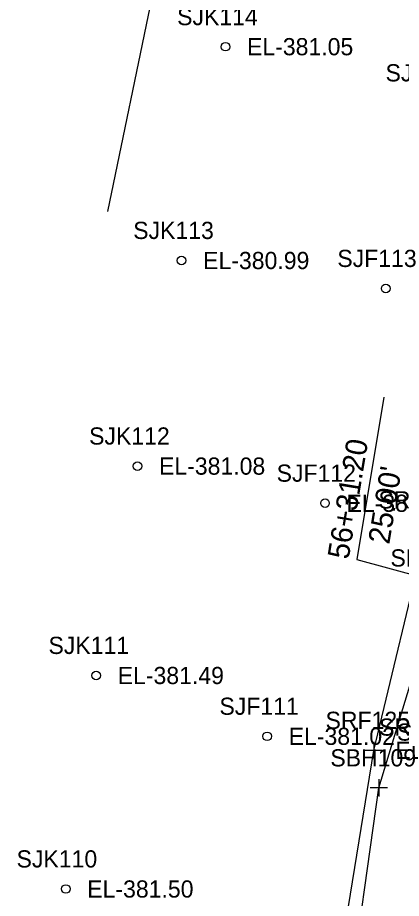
# Model space of a CAD drawing. Extents: x 1189978 to 1314812, y 571533 to 629339.
# Drawn here: x 1217347.2 to 1217436.4, y 621309.2 to 621514.1 of the extents above; entities that cross this region are included whole.
import ezdxf

# ---------------------------------------------------------------- set-up
doc = ezdxf.new("R2010")
doc.units = 0
for name, color, linetype in [('SURVEY - DRAINAGE - Bridge Hydraulic Data with Text', 7, 'Continuous'), ('SURVEY - DTM - Breaklines', 7, 'Continuous'), ('SURVEY - DTM - Breaklines - Points - Elevations', 7, 'Continuous'), ('SURVEY - DTM - Breaklines - Points - Locators', 7, 'Continuous'), ('SURVEY - DTM - Breaklines - Points - Numbers', 7, 'Continuous'), ('SURVEY - DTM - Spot Points - Elevations', 7, 'Continuous'), ('SURVEY - DTM - Spot Points - Locators', 7, 'Continuous'), ('SURVEY - DTM - Spot Points - Point Numbers', 7, 'Continuous'), ('SURVEY - PROPERTY - Station and Offset Flags', 7, 'Continuous'), ('SURVEY - VEGETATION - Features - Points - Locators', 7, 'Continuous'), ('SURVEY - VEGETATION - Features - Points - Numbers', 7, 'Continuous'), ('SURVEY - VEGETATION - Features with Text', 7, 'Continuous')]:
    doc.layers.add(name, color=color, linetype=linetype)

msp = doc.modelspace()

# ---------------------------------------------------------------- linework, layer by layer
at = {"layer": 'SURVEY - DRAINAGE - Bridge Hydraulic Data with Text'}
msp.add_line((1217368.17, 621469.01), (1217394.49, 621596.22), dxfattribs=at)
at = {"layer": 'SURVEY - DTM - Breaklines'}
msp.add_lwpolyline([(1217387.31, 620948.08), (1217393.6, 620996.48), (1217397.69, 621051.02), (1217403.2, 621099.03), (1217410.14, 621143.75), (1217412.38, 621196.49), (1217416.71, 621248.1), (1217421.59, 621292.12), (1217429.99, 621343.65), (1217442.32, 621394.91), (1217455.15, 621442.51), (1217467.64, 621488.57), (1217479.21, 621534.19), (1217491.95, 621583.57), (1217498.28, 621637.4), (1217497.56, 621661.82), (1217450.04, 621674.51)], dxfattribs=at)
at = {"layer": 'SURVEY - DTM - Breaklines - Points - Locators'}
for p, q in [((1217429.99, 621345.65), (1217429.99, 621341.65)), ((1217431.99, 621343.65), (1217427.99, 621343.65))]:
    msp.add_line(p, q, dxfattribs=at)
at = {"layer": 'SURVEY - DTM - Spot Points - Locators'}
for centre in [(1217395.51, 621507.3), (1217385.31, 621457.58), (1217432.73, 621451.07), (1217375.06, 621409.77), (1217418.63, 621401.13), (1217365.46, 621361.08), (1217405.19, 621346.93), (1217358.39, 621311.43)]:
    msp.add_circle(centre, 1, dxfattribs=at)
at = {"layer": 'SURVEY - PROPERTY - Station and Offset Flags'}
msp.add_line((1217432.26, 621425.81), (1217426.02, 621388.03), dxfattribs=at)
msp.add_lwpolyline([(1217426.02, 621388.03), (1217500.7, 621367.73)], dxfattribs=at)
at = {"layer": 'SURVEY - VEGETATION - Features - Points - Locators'}
for p, q in [((1217431.12, 621336.93), (1217431.12, 621332.93)), ((1217433.12, 621334.93), (1217429.12, 621334.93))]:
    msp.add_line(p, q, dxfattribs=at)
at = {"layer": 'SURVEY - VEGETATION - Features with Text'}
msp.add_lwpolyline([(1217389.81, 620940.03), (1217391.17, 620986.93), (1217395.55, 621035.23), (1217406.85, 621081.03), (1217411.05, 621130.02), (1217415.5, 621179.49), (1217417.45, 621231.25), (1217423.95, 621283.66), (1217431.12, 621334.93), (1217445.24, 621381.42), (1217454.29, 621426.66), (1217468.2, 621478.56), (1217483.94, 621529.19), (1217494.32, 621578.08), (1217503.06, 621624.42), (1217502.76, 621670.78), (1217560.76, 621675.93)], dxfattribs=at)

# ---------------------------------------------------------------- texts
at = {"layer": 'SURVEY - DTM - Breaklines - Points - Elevations'}
msp.add_text('EL-381.97', height=4, dxfattribs=at).set_placement((1217434.99, 621341.65))
at = {"layer": 'SURVEY - DTM - Breaklines - Points - Numbers'}
for s, p in [('SRF128', (1217431.04, 621399.91)), ('SRF125', (1217418.75, 621348.65)), ('SRF126', (1217431.16, 621347.08)), ('SRF127', (1217435.34, 621345.92))]:
    msp.add_text(s, height=4, dxfattribs=at).set_placement(p)
at = {"layer": 'SURVEY - DTM - Spot Points - Elevations'}
for s, p in [('EL-381.05', (1217400.51, 621505.3)), ('EL-380.99', (1217390.31, 621455.58)), ('EL-381.08', (1217380.06, 621407.77)), ('EL-380.95', (1217423.63, 621399.13)), ('EL-381.49', (1217370.46, 621359.08)), ('EL-381.02', (1217410.19, 621344.93)), ('EL-381.50', (1217363.39, 621309.43))]:
    msp.add_text(s, height=4, dxfattribs=at).set_placement(p)
at = {"layer": 'SURVEY - DTM - Spot Points - Point Numbers'}
for s, p in [('SJK114', (1217384.27, 621512.3)), ('SJF114', (1217432.69, 621499.22)), ('SJK113', (1217374.07, 621462.58)), ('SJF113', (1217421.49, 621456.07)), ('SJK112', (1217363.82, 621414.77)), ('SJF112', (1217407.39, 621406.13)), ('SJK111', (1217354.38, 621366.08)), ('SJF111', (1217394.1, 621351.93)), ('SJK110', (1217346.97, 621316.43))]:
    msp.add_text(s, height=4, dxfattribs=at).set_placement(p)
at = {"layer": 'SURVEY - PROPERTY - Station and Offset Flags'}
for s, p in [('56+31.20', (1217424.1, 621387.91)), ("25.00'", (1217433.55, 621391.43))]:
    msp.add_text(s, height=5, rotation=80.6236, dxfattribs=at).set_placement(p)
at = {"layer": 'SURVEY - VEGETATION - Features - Points - Numbers'}
for s, p in [('SBH110', (1217433.83, 621386.42)), ('SBH109', (1217419.87, 621339.93))]:
    msp.add_text(s, height=4, dxfattribs=at).set_placement(p)

doc.saveas('drawing.dxf')
